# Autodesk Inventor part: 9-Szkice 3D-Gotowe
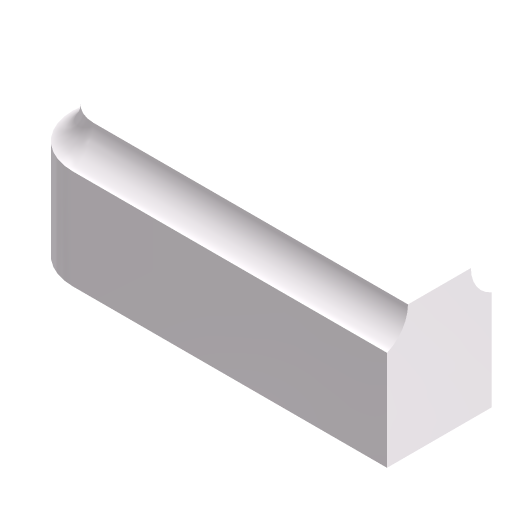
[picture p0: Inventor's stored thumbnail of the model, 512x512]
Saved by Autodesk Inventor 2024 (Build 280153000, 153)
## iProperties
Company: ATC
Shininess: 21.0
Length Units: 11269
Angle Units: 11279
Time Units: 11290
Mass Units: 11283
Compacted: True
Created: 2023-03
Part Number: 9-Szkice 3D-Gotowe
Document SubType Name: Modeling
Designer: Andrzej Jaskulski
Material: Kurs-AJ
Density: 1 g/cm^3
Appearance: Kurs-AJ
Checked By: A.J.
Engr Approved By: Andrzej Jaskulski
Mfg Approved By: Andrzej Jaskulski
Authority: A.J.
Density: 0.0
Volumn: 0.0
Area: 0.0
PropertySet Name: Model Information
Control State: 0
Master: False
Checked Out: False
Title: A.J.: Kurs R2024-MEP
Author: Andrzej Jaskulski
Revision Number: 1/24
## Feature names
1. Baza [Extrusion]
2. Zaokrąglenie [Fillet]
3. Frezowanie
## Parameters: d1 = 0, d2 = 90 deg, d7 = 25 mm, d8 = 25 mm, d9 = 26 mm, d10 = 0, d104 = 0
